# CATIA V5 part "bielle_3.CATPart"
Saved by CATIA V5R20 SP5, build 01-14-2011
Part number: bielle_3
Bounding box of the stored display mesh (mm): x 5 to 10, y -95 to 5, z 95 to 105
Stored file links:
  U:\2A\IAO\ThinkMotion\bielle_3.CATPart
  U:\2A\IAO\ThinkMotion\MECANISME 1517.CATProduct
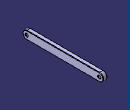
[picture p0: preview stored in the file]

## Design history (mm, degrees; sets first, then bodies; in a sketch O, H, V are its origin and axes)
Set1
  Plane1 "Plan_ref": linked copy from another document
  Point1: linked copy from another document
  Point2: linked copy from another document
Body1 (main body)
  Sketch1 on Plane1, origin (0, 0, 0), H (0, 1, 0), V (0, 0, 1)
    construction line L1 (-90, 100) -> (0, 100)
    point P1 (0, 100)
    point P2 (-90, 100)
    line L2 (-90, 105) -> (0, 105)
    line L3 (0, 95) -> (-90, 95)
    arc A1 centre (0, 100) radius 5 from (0, 105) to (0, 95) cw
    arc A2 centre (-90, 100) radius 5 from (-90, 95) to (-90, 105) cw
    reference projected point E1 (0, 100) from Point1
    reference projected point E2 (-90, 100) from Point2
    distance L1 L2 = 5
    coincidence: P1 V, E1 P1, P2 E2
    horizontal: L1 H
    tangency: A1 L2, A2 L2, A1 L3, A2 L3
  Pad1: profile Sketch1, direction (1, 0, 0), length 10
  Sketch2 on end face of Pad1, origin (10, 0, 100), H (0, 1, 0), V (0, 0, 1)
    point P1 (0, 0)
    reference projected point E1 (0, 0) from Point1
    coincidence: E1 P1
  Hole1: placed by Sketch2, at (10, 0, 100) direction (-1, 0, 0), diameter 3, through (limit type 3)
  Sketch3 on Plane1, origin (0, 0, 0), H (0, 1, 0), V (0, 0, 1)
    construction line L1 (-90, 100) -> (0, 100)
    point P1 (-90, 100)
    point P2 (0, 100)
    line L2 (-90, 105) -> (0, 105)
    line L3 (0, 95) -> (-90, 95)
    arc A1 centre (0, 100) radius 5 from (0, 105) to (0, 95) cw
    arc A2 centre (-90, 100) radius 5 from (-90, 95) to (-90, 105) cw
    reference projected point E1 (-90, 100) from Point2
    reference projected point E2 (0, 100) from Point1
    distance L1 L2 = 5
    horizontal: L1 H
    tangency: A1 L2, A2 L2, A1 L3, A2 L3
    coincidence: P1 E1, P2 E2
  Pocket1: profile Sketch3, direction (1, 0, 0), length 5
  Sketch4 on end face of Pad1, origin (10, -90, 100), H (0, 1, 0), V (0, 0, 1)
    point P1 (0, 0)
    reference projected point E1 (0, 0) from Point2
    coincidence: E1 P1
  Hole2: placed by Sketch4, at (10, -90, 100) direction (-1, 0, 0), diameter 3, through (limit type 3)
  Fillet1: radius 0.5, on end face of Pad1; end face of Pocket1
